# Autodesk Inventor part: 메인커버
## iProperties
Manager: KYOUNG IL JANG
Company: 한국ATC센터
Created: 2012-10
Part Number: 메인커버
Document SubType Name: Modeling
Density: 1 g/cm^3
Checked By: KYOUNG IL JANG
Vendor: CBT Solutions
Designer: KYOUNG IL JANG
Author: KYOUNG IL JANG
